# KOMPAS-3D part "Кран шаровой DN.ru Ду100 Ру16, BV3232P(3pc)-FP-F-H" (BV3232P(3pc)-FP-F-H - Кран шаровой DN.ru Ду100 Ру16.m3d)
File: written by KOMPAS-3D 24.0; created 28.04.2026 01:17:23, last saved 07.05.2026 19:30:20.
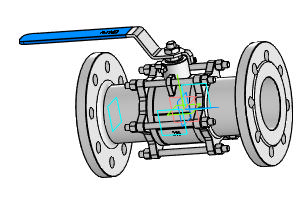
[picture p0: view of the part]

Document properties: Автор: Максим; Полное имя файла: BVxxP(3pc)-FP-F-H - Кран шаровой DN.ru Ду100 Ру16.cdw

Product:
- Body: Тело 1  | qty 1
    Масса: 22.220503
- Part/product: Кран шаровой DN.ru Ду100 Ру16  | designation BV3232P(3pc)-FP-F-H
    Масса: 25.675
    Раздел спецификации: Прочие изделия
    Форматы листов документа: A3
    Примечание: D160-22809

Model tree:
1. Операция без истории:1
2. Эскиз:1  (with: Ребро.Операция без истории:1)
3. Элемент выдавливания:1
     Расстояние 1 = 14
4. Скругление:1  (with: Ребро.Элемент выдавливания:1)
     Радиус = 5.2
5. Скругление:2  (with: Ребро.Элемент выдавливания:1)
     Радиус = 10.4
6. Эскиз:2  (with: Ребро.Элемент выдавливания:1)
7. Элемент выдавливания:2
     Расстояние 1 = 41
8. Фаска:1  (with: Ребро.Элемент выдавливания:2)
     Угол = 45; Длина 1 = 12; Длина 2 = 12
9. Скругление:3  (with: Ребро.Элемент выдавливания:1)
     Радиус = 5.2
10. Скругление:4  (with: Ребро.Элемент выдавливания:1)
     Радиус = 10.4
11. Эскиз:3  (with: Ребро.Элемент выдавливания:2)
12. Элемент выдавливания:3
     Расстояние 1 = 42
13. Скругление:5  (with: Ребро.Элемент выдавливания:3)
     Радиус = 13
14. Скругление:6  (with: Ребро.Элемент выдавливания:3)
     Радиус = 0.5
15. Эскиз:4  (with: Грань.Операция без истории:1, Ребро.Операция без истории:1)
16. Элемент выдавливания:4  (with: Грань.Операция без истории:1)
     Расстояние 2 = 350
17. Смещенная плоскость:1
     Расстояние = -141
18. Эскиз:5  (with: Ребро.Операция без истории:1)
19. Элемент выдавливания:5
     Расстояние 2 = 45
20. Зеркальный массив:1
21. Экземпляр ( 1 )
22. Экземпляр ( 2 )  (with: Элемент выдавливания:5)
23. Смещенная плоскость:2
     Расстояние = 68
24. Эскиз:6
25. Элемент выдавливания:6  (with: Грань.Операция без истории:1)
     Расстояние 1 = -10.0363
26. Эскиз:7
27. Элемент выдавливания:7
     Расстояние 1 = 66
28. Эскиз:8  (with: Грань.Операция без истории:1, Ребро.Операция без истории:1)
29. Элемент выдавливания:8  (with: Грань.Операция без истории:1)
     Расстояние 1 = -21
30. Эскиз:9  (with: Грань.Операция без истории:1, Ребро.Операция без истории:1)
31. Элемент выдавливания:10  (with: Грань.Операция без истории:1)
     Расстояние 1 = -21
32. Эскиз:10  (with: Грань.Операция без истории:1)
33. Элемент выдавливания:11  (with: Грань.Операция без истории:1)
     Расстояние 1 = 50
34. Зеркальный массив:2  (with: Экземпляр ( 1 ), Экземпляр ( 2 ), Элемент выдавливания:11)
35. Эскиз:12  (with: Грань.Операция без истории:1)
36. Элемент выдавливания:13
     Расстояние 1 = 10
37. Зеркальный массив:3  (with: Экземпляр ( 1 ), Экземпляр ( 2 ), Элемент выдавливания:13)
38. Эскиз:13  (with: Грань.Элемент выдавливания:13, Ребро.Операция без истории:1)
39. Элемент вращения:1
     Угол 1 = 360
40. Зеркальный массив:4  (with: Экземпляр ( 1 ), Экземпляр ( 2 ), Элемент вращения:1)
41. Элемент выдавливания:14
     Расстояние 1 = 50
42. Зеркальный массив:5  (with: Экземпляр ( 1 ), Экземпляр ( 2 ), Элемент выдавливания:14)
43. Смещенная плоскость:3
     Расстояние = 68
44. Эскиз:14
45. Элемент выдавливания:15  (with: Грань.Операция без истории:1)
     Расстояние 1 = -10.8895
46. Зеркальный массив:6  (with: Экземпляр ( 1 ), Экземпляр ( 2 ), Элемент выдавливания:7)
47. Эскиз:15  (with: Грань.Элемент выдавливания:3, Ребро.Скругление:6, Ребро.Элемент выдавливания:3)
48. Элемент выдавливания:16
     Расстояние 2 = 0.2

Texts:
  BV3232P(3pc)-FP-F-H
  DN100 PN16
